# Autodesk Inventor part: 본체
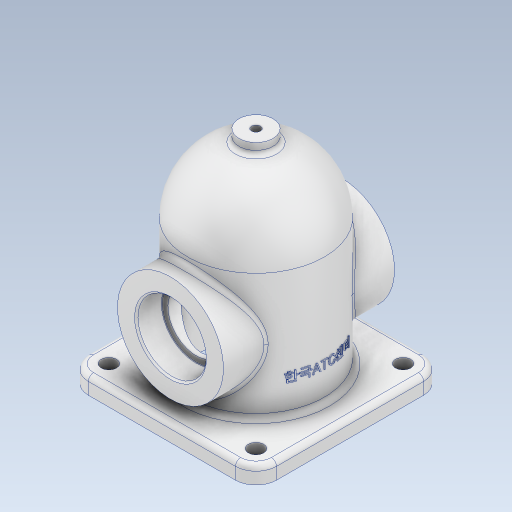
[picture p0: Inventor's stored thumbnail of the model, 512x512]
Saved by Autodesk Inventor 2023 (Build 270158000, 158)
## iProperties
Created: 2025-04
Part Number: 본체
Material: 알루미늄 6061
Document SubType Name: Modeling
Designer: Admin
Density: 2.7 g/cm^3
Appearance: 알루미늄 - 평지
Author: Admin
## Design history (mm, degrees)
sketch "스케치2"
  geometry: L1 (0, 42)-(40, 42); L2 (40, 42)-(40, -42); L3 (40, -42)-(0, -42); L4 (0, -42)-(0, 42); L5 (-9.657, 0)-(57.941, 0) reference; L6 (0, 82)-(0, 42); L7 (0, -68.457)-(0, 116.741) reference; A1 r 40 centre (0, 42) between (40, 42) and (0, 82); 2 further points
  constraints: 10 end point, 2 parallel, 2 point on circle, 1 centre point, 1 coincident, 1 horizontal, 1 midpoint, 1 perpendicular, 1 vertical
  dimensions: "d5" = 40 distance of L2.end L3.end; "d6" = 84 distance of L1.end L2.end; "d7" = 42 distance between parallel lines of L5 L1
revolve "회전1" sketch "스케치2" stored, may be unused: angle "d8" = 90 deg
sketch "스케치3"
  geometry: L1 (0, -67.8)-(0, 112.8) reference; L2 (40, -42)-(-40, -42) reference; C1 r 31 at (0, 6); 1 further point
  constraints: 1 centre point, 1 coincident, 1 point on line
  dimensions: "d9" = 62 diameter of C1; "d22" = 48 distance from line of L2 point (0, 6)
extrude "돌출1" join sketch "스케치3" stored distance "d10" = 100; taper "d11" = 0 deg
sketch "스케치4"
  geometry: L1 (-55, -55)-(55, -55); L2 (55, -55)-(55, 55); L3 (55, 55)-(-55, 55); L4 (-55, 55)-(-55, -55); L5 (-55, -55)-(55, 55); L6 (55, -55)-(-55, 55); 1 further point
  constraints: 12 end point, 2 midpoint, 2 parallel, 1 horizontal, 1 perpendicular
  dimensions: "d12" = 110 distance of L3.end L2.end; "d13" = 110 distance of L2.end L1.end
extrude "돌출2" join sketch "스케치4" distance "d14" = 10; taper "d15" = 0 deg
sketch "스케치5"
  geometry: C1 r 10 at (55, -55); 1 further point
  constraints: 1 centre point, 1 coincident
  dimensions: "d16" = 20 diameter of C1
extrude "돌출3" join sketch "스케치5" distance "d17" = 129; taper "d18" = 0 deg
sketch "스케치6"
  geometry: L1 (42, -40)-(42, 40) reference; L2 (42, -32)-(-42, -32); L3 (-42, 55)-(-42, -55) reference; L4 (-42, 0)-(-42, -32); L5 (-42, 0)-(74, 0); A1 r 32 centre (42, 0) between (42, -32) and (74, 0); 2 further points
  constraints: 6 end point, 2 perpendicular, 2 point on circle, 2 point on line, 1 centre point, 1 horizontal, 1 midpoint
  dimensions: "d19" = 32 radius of A1; "d20" = 84 distance of L2.start L2.end
revolve "회전2" sketch "스케치6" stored, may be unused: angle "d21" = 90 deg
sketch "스케치7"
  geometry: L1 (37, 50)-(-25, 50) reference; L2 (6, 50)-(6, -50); L3 (-25, -50)-(37, -50) reference; L4 (6, 50)-(26, 50); L5 (26, 50)-(26, 35); L6 (26, 35)-(6, 35); L7 (6, 35)-(6, 50); L8 (6, -50)-(26, -50); L9 (26, -50)-(26, -35); L10 (26, -35)-(6, -35); L11 (6, -35)-(6, -50); L12 (6, 35)-(22.5, 35); L13 (22.5, 35)-(22.5, -35); L14 (22.5, -35)-(6, -35); L15 (6, -35)-(6, 35); L16 (-67.8, 0)-(112.8, 0) reference; 4 further points
  constraints: 26 end point, 6 parallel, 3 horizontal, 3 perpendicular, 2 midpoint, 2 point on line, 1 other
  dimensions: "d23" = 40 diameter of L5 L2; "d24" = 33 diameter of L13 L2; "d25" = 15 distance between parallel lines of L4 L12
revolve "회전3" sketch "스케치7" stored, may be unused: angle "d26" = 90 deg
sketch "스케치8"
  geometry: L1 (-43, -43)-(43, -43); L2 (43, -43)-(43, 43); L3 (43, 43)-(-43, 43); L4 (-43, 43)-(-43, -43); L5 (-43, -43)-(43, 43); L6 (43, -43)-(-43, 43); C1 r 4.5 at (-43, -43); 1 further point
  constraints: 12 end point, 2 midpoint, 2 parallel, 1 centre point, 1 coincident, 1 horizontal, 1 perpendicular
  dimensions: "d27" = 86 distance of L3.end L2.end; "d28" = 86 distance of L2.end L1.end; "d29" = 9 diameter of C1
extrude "돌출4" cut sketch "스케치8" extent not by distance; stored distance "d30" = 0; taper "d31" = 0 deg
sketch "스케치9"
  geometry: 2 further points
  constraints: 1 coincident
hole "구멍1" sketch "스케치9" at (0, 0) diameter "d38" = 5.1881; stored, may be unused: countersink angle "d42" = 90 deg, drill point angle "d44" = 0 deg; dims "d39" = 12, "d40" = 4, "d41" = 2, "d43" = 16
fillet "모깎기1" dims "d45" = 12
fillet "모깎기2" dims "d46" = 3
chamfer "모따기1" distance "d47" = 1; stored, may be unused: second distance "d48" = 2, angle "d49" = 45 deg
fillet "모깎기3" dims "d50" = 0.3
fillet "모깎기4" dims "d51" = 3
node "작업 평면1"
sketch "스케치10"
  geometry: L1 (-42, -43)-(-42, 43) reference; L2 (-67.8, 0)-(112.8, 0) reference; 2 further points
  constraints: 1 point on line, 1 other
  dimensions: "d53" = 30 distance from line of L1 point (-12, 0)
feature "엠보싱1" sketch "스케치10" dims "d5" = 40, "d54" = 0.5, "d55" = 0
node "솔리드1"
pattern_linear "직사각형 패턴1" dims "d34" = 86, "d37" = 86
feature "A9D066F2-1C7D-4E18-AEED-F7BC21143FA4" dims "d38" = 5.1881, "d39" = 12, "d40" = 4, "d41" = 2, "d42" = 90 deg, "d43" = 16, "d44" = 0
other parameters: "d52" = 46.0375
